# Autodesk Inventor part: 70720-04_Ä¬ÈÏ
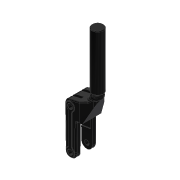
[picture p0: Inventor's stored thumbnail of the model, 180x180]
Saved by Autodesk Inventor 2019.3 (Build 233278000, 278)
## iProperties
Created: 2010-06
Part Number: 70720-04_Ä¬ÈÏ
Material: Ogólny
Document SubType Name: Modeling
Designer: CADENGINEERING4
Density: 1 g/cm^3
Appearance: Gładki — czarny
Author: CADENGINEERING4
Revision Number: ÈÎºÎ
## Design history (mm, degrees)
feature "NONE"
node "Bryła1"
